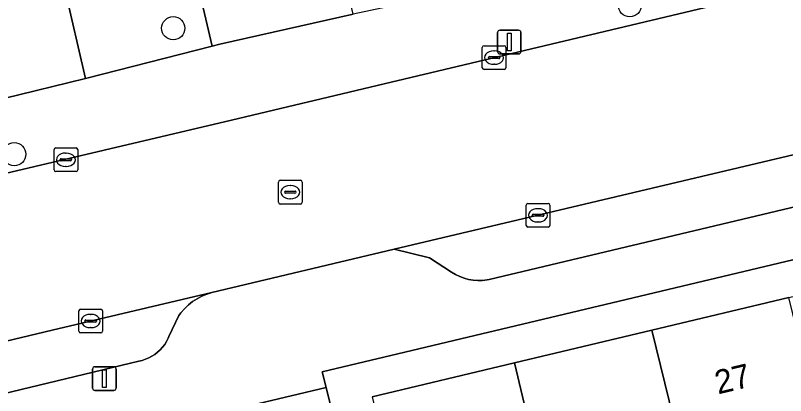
# Model space of a CAD drawing. Extents: x 158031 to 159244, y 380104 to 381214.
# Drawn here: x 158418.58 to 158451.04, y 380830.93 to 380846.95 of the extents above; entities that cross this region are included whole.
import ezdxf

# ---------------------------------------------------------------- set-up
doc = ezdxf.new("R2010")
doc.units = 0
for name, color, linetype in [('IMGEO_Boom', 7, 'Continuous'), ('IMGEO_Erf', 7, 'Continuous'), ('IMGEO_Groenvoorziening', 7, 'Continuous'), ('IMGEO_Kolk', 7, 'Continuous'), ('IMGEO_Lichtmast', 7, 'Continuous'), ('IMGEO_Pand', 7, 'Continuous'), ('IMGEO_Pand_nummerreeks', 7, 'Continuous'), ('IMGEO_Parkeervlak_open', 7, 'Continuous'), ('IMGEO_Rijbaan_lokaal_open', 7, 'Continuous'), ('IMGEO_Rioolput', 7, 'Continuous'), ('IMGEO_Voetpad_open', 7, 'Continuous')]:
    doc.layers.add(name, color=color, linetype=linetype)

msp = doc.modelspace()

# ---------------------------------------------------------------- linework, layer by layer
at = {"layer": 'IMGEO_Boom'}
for centre in [(158444.473, 380847.384), (158425.228, 380846.411), (158418.528, 380841.1)]:
    msp.add_circle(centre, 0.489, dxfattribs=at)
at = {"layer": 'IMGEO_Erf'}
for points in [[(158492.147, 380846.362), (158431.507, 380831.934), (158431.67, 380831.273), (158437.015, 380809.671), (158479.606, 380819.978)], [(158433.619, 380830.882), (158439.614, 380832.308), (158445.404, 380833.686), (158451.175, 380835.059), (158457.004, 380836.446), (158457.353, 380835.07), (158457.487, 380835.102), (158458.165, 380835.263), (158459.767, 380835.644), (158460.083, 380834.315), (158463.733, 380835.183), (158467.394, 380836.054), (158467.081, 380837.368), (158469.197, 380837.871)]]:
    msp.add_lwpolyline(points, dxfattribs=at)
at = {"layer": 'IMGEO_Groenvoorziening'}
msp.add_lwpolyline([(158426.008, 380849.326), (158421.836, 380848.384), (158420.64, 380848.128), (158421.532, 380844.298), (158426.87, 380845.655)], close=True, dxfattribs=at)
at = {"layer": 'IMGEO_Kolk'}
for p, q in [((158438.253, 380844.746), (158438.253, 380845.598)), ((158438.328, 380845.672), (158439.18, 380845.672)), ((158439.254, 380845.598), (158439.254, 380844.746)), ((158438.512, 380845.166), (158438.512, 380845.178)), ((158438.555, 380845.215), (158438.953, 380845.215)), ((158438.741, 380845.452), (158438.766, 380845.452)), ((158438.996, 380845.178), (158438.996, 380845.166)), ((158438.95, 380845.129), (158438.552, 380845.129)), ((158438.764, 380844.892), (158438.739, 380844.892)), ((158439.18, 380844.672), (158438.328, 380844.672)), ((158420.204, 380840.443), (158420.204, 380841.295)), ((158420.279, 380841.369), (158421.131, 380841.369)), ((158421.205, 380841.295), (158421.205, 380840.443)), ((158420.692, 380841.149), (158420.717, 380841.149)), ((158420.463, 380840.863), (158420.463, 380840.875)), ((158420.901, 380840.826), (158420.503, 380840.826)), ((158420.506, 380840.912), (158420.904, 380840.912)), ((158420.947, 380840.875), (158420.947, 380840.863)), ((158421.131, 380840.369), (158420.279, 380840.369)), ((158420.715, 380840.589), (158420.69, 380840.589)), ((158440.179, 380839.027), (158441.031, 380839.027)), ((158440.104, 380838.101), (158440.104, 380838.953)), ((158440.592, 380838.807), (158440.617, 380838.807)), ((158441.105, 380838.953), (158441.105, 380838.101)), ((158440.363, 380838.521), (158440.363, 380838.533)), ((158440.801, 380838.484), (158440.403, 380838.484)), ((158440.406, 380838.57), (158440.804, 380838.57)), ((158440.847, 380838.533), (158440.847, 380838.521)), ((158441.031, 380838.027), (158440.179, 380838.027)), ((158440.615, 380838.247), (158440.59, 380838.247)), ((158421.249, 380833.646), (158421.249, 380834.498)), ((158421.324, 380834.572), (158422.176, 380834.572)), ((158422.25, 380834.498), (158422.25, 380833.646)), ((158421.551, 380834.115), (158421.949, 380834.115)), ((158421.737, 380834.352), (158421.762, 380834.352)), ((158421.508, 380834.066), (158421.508, 380834.078)), ((158421.946, 380834.029), (158421.548, 380834.029)), ((158421.76, 380833.792), (158421.735, 380833.792)), ((158421.992, 380834.078), (158421.992, 380834.066)), ((158422.176, 380833.572), (158421.324, 380833.572))]:
    msp.add_line(p, q, dxfattribs=at)
for points in [[(158438.253, 380844.746), (158438.253, 380845.598)], [(158438.328, 380845.672), (158439.18, 380845.672)], [(158439.254, 380845.598), (158439.254, 380844.746)], [(158439.18, 380844.672), (158438.328, 380844.672)], [(158420.204, 380840.443), (158420.204, 380841.295)], [(158420.279, 380841.369), (158421.131, 380841.369)], [(158421.205, 380841.295), (158421.205, 380840.443)], [(158421.131, 380840.369), (158420.279, 380840.369)], [(158440.179, 380839.027), (158441.031, 380839.027)], [(158440.104, 380838.101), (158440.104, 380838.953)], [(158441.105, 380838.953), (158441.105, 380838.101)], [(158441.031, 380838.027), (158440.179, 380838.027)], [(158421.249, 380833.646), (158421.249, 380834.498)], [(158421.324, 380834.572), (158422.176, 380834.572)], [(158422.25, 380834.498), (158422.25, 380833.646)], [(158422.176, 380833.572), (158421.324, 380833.572)]]:
    msp.add_lwpolyline(points, dxfattribs=at)
for centre, radius, start, end in [((158438.33, 380845.596), 0.0765, 91.552, 178.448), ((158438.33, 380845.596), 0.0765, 91.552, 178.448), ((158439.178, 380845.596), 0.0765, 1.552, 88.448), ((158439.178, 380845.596), 0.0765, 1.552, 88.448), ((158438.552, 380845.175), 0.0403, 85.8775, 175.7526), ((158438.549, 380845.165), 0.0366, 178.938, 274.7102), ((158438.953, 380845.172), 0.043, 264.8664, 352.4533), ((158438.957, 380845.177), 0.0386, 1.7309, 96.639), ((158438.33, 380844.748), 0.0765, 181.552, 268.448), ((158438.33, 380844.748), 0.0765, 181.552, 268.448), ((158439.178, 380844.748), 0.0765, 271.552, 358.448), ((158439.178, 380844.748), 0.0765, 271.552, 358.448), ((158420.281, 380841.293), 0.0765, 91.552, 178.448), ((158420.281, 380841.293), 0.0765, 91.552, 178.448), ((158421.129, 380841.293), 0.0765, 1.552, 88.448), ((158421.129, 380841.293), 0.0765, 1.552, 88.448), ((158420.503, 380840.872), 0.0403, 85.8775, 175.7526), ((158420.5, 380840.862), 0.0366, 178.938, 274.7102), ((158420.904, 380840.869), 0.043, 264.8664, 352.4533), ((158420.908, 380840.874), 0.0386, 1.7309, 96.639), ((158420.281, 380840.445), 0.0765, 181.552, 268.448), ((158420.281, 380840.445), 0.0765, 181.552, 268.448), ((158421.129, 380840.445), 0.0765, 271.552, 358.448), ((158421.129, 380840.445), 0.0765, 271.552, 358.448), ((158440.181, 380838.951), 0.0765, 91.552, 178.448), ((158440.181, 380838.951), 0.0765, 91.552, 178.448), ((158441.029, 380838.951), 0.0765, 1.552, 88.448), ((158441.029, 380838.951), 0.0765, 1.552, 88.448), ((158440.403, 380838.53), 0.0403, 85.8775, 175.7526), ((158440.4, 380838.52), 0.0366, 178.938, 274.7102), ((158440.804, 380838.527), 0.043, 264.8664, 352.4533), ((158440.808, 380838.532), 0.0386, 1.7309, 96.639), ((158440.181, 380838.103), 0.0765, 181.552, 268.448), ((158440.181, 380838.103), 0.0765, 181.552, 268.448), ((158441.029, 380838.103), 0.0765, 271.552, 358.448), ((158441.029, 380838.103), 0.0765, 271.552, 358.448), ((158421.326, 380834.496), 0.0765, 91.552, 178.448), ((158421.326, 380834.496), 0.0765, 91.552, 178.448), ((158422.174, 380834.496), 0.0765, 1.552, 88.448), ((158422.174, 380834.496), 0.0765, 1.552, 88.448), ((158421.548, 380834.075), 0.0403, 85.8775, 175.7526), ((158421.953, 380834.077), 0.0386, 1.7309, 96.639), ((158421.545, 380834.065), 0.0366, 178.938, 274.7102), ((158421.949, 380834.072), 0.043, 264.8664, 352.4533), ((158421.326, 380833.648), 0.0765, 181.552, 268.448), ((158421.326, 380833.648), 0.0765, 181.552, 268.448), ((158422.174, 380833.648), 0.0765, 271.552, 358.448), ((158422.174, 380833.648), 0.0765, 271.552, 358.448)]:
    msp.add_arc(centre, radius, start, end, dxfattribs=at)
for centre, major_axis, ratio, start_param, end_param in [((158438.74, 380845.172), (-0.387, 0.002), 0.722429, 4.712389, 7.853982), ((158438.765, 380845.172), (-0.39, 0.002), 0.717154, 1.570796, 4.712389), ((158420.691, 380840.869), (-0.387, 0.002), 0.722429, 4.712389, 7.853982), ((158420.716, 380840.869), (-0.39, 0.002), 0.717154, 1.570796, 4.712389), ((158440.591, 380838.527), (-0.387, 0.002), 0.722429, 4.712389, 7.853982), ((158440.616, 380838.527), (-0.39, 0.002), 0.717154, 1.570796, 4.712389), ((158421.736, 380834.072), (-0.387, 0.002), 0.722429, 4.712389, 7.853982), ((158421.761, 380834.072), (-0.39, 0.002), 0.717154, 1.570796, 4.712389)]:
    msp.add_ellipse(centre, major_axis=major_axis, ratio=ratio, start_param=start_param, end_param=end_param, dxfattribs=at)
at = {"layer": 'IMGEO_Lichtmast'}
for p, q in [((158438.896, 380845.429), (158438.896, 380846.229)), ((158438.896, 380846.229), (158438.896, 380845.429)), ((158438.996, 380846.329), (158439.786, 380846.329)), ((158439.786, 380846.329), (158438.996, 380846.329)), ((158439.886, 380846.229), (158439.886, 380845.429)), ((158439.886, 380845.429), (158439.886, 380846.229)), ((158439.786, 380845.329), (158438.996, 380845.329)), ((158438.996, 380845.329), (158439.786, 380845.329)), ((158421.829, 380831.247), (158421.829, 380832.047)), ((158421.829, 380832.047), (158421.829, 380831.247)), ((158421.929, 380832.147), (158422.719, 380832.147)), ((158422.719, 380832.147), (158421.929, 380832.147)), ((158422.819, 380832.047), (158422.819, 380831.247)), ((158422.819, 380831.247), (158422.819, 380832.047)), ((158422.719, 380831.147), (158421.929, 380831.147)), ((158421.929, 380831.147), (158422.719, 380831.147))]:
    msp.add_line(p, q, dxfattribs=at)
for points in [[(158439.316, 380846.204), (158439.466, 380846.204), (158439.466, 380845.454), (158439.316, 380845.454), (158439.316, 380846.204)], [(158422.249, 380832.022), (158422.399, 380832.022), (158422.399, 380831.272), (158422.249, 380831.272), (158422.249, 380832.022)]]:
    msp.add_lwpolyline(points, dxfattribs=at)
for centre, start, end in [((158438.996, 380846.229), 90, 180), ((158438.996, 380846.229), 90, 180), ((158439.786, 380846.229), 0, 90), ((158439.786, 380846.229), 360, 90), ((158438.996, 380845.429), 180, 270), ((158438.996, 380845.429), 180, 270), ((158439.786, 380845.429), 270, 0), ((158439.786, 380845.429), 270, 0), ((158421.929, 380832.047), 90, 180), ((158421.929, 380832.047), 90, 180), ((158422.719, 380832.047), 0, 90), ((158422.719, 380832.047), 360, 90), ((158421.929, 380831.247), 180, 270), ((158421.929, 380831.247), 180, 270), ((158422.719, 380831.247), 270, 0), ((158422.719, 380831.247), 270, 0)]:
    msp.add_arc(centre, 0.1, start, end, dxfattribs=at)
at = {"layer": 'IMGEO_Pand'}
for points in [[(158451.175, 380835.059), (158445.404, 380833.686), (158447.591, 380824.752), (158451.78, 380825.749), (158453.052, 380820.399), (158454.671, 380820.784)], [(158442.999, 380818.07), (158444.915, 380818.526), (158443.656, 380823.816), (158447.591, 380824.752), (158445.404, 380833.686), (158439.614, 380832.308)], [(158442.999, 380818.07), (158439.614, 380832.308), (158433.619, 380830.882), (158434.776, 380826.018), (158435.727, 380822.023), (158440.038, 380823.049), (158441.318, 380817.67)]]:
    msp.add_lwpolyline(points, close=True, dxfattribs=at)
at = {"layer": 'IMGEO_Parkeervlak_open'}
msp.add_lwpolyline([(158470.273, 380843.365), (158469.788, 380845.423), (158465.626, 380844.441), (158434.542, 380837.096), (158436.031, 380836.73), (158436.953, 380836.125), (158437.123, 380836.027), (158437.302, 380835.944), (158437.487, 380835.878), (158437.678, 380835.828), (158437.872, 380835.796), (158438.068, 380835.781), (158438.265, 380835.783), (158438.46, 380835.804), (158438.55, 380835.819)], close=True, dxfattribs=at)
msp.add_lwpolyline([(158403.115, 380827.409), (158423.774, 380832.383), (158423.919, 380832.415), (158424.061, 380832.459), (158424.199, 380832.516), (158424.33, 380832.585), (158424.455, 380832.666), (158424.572, 380832.757), (158424.681, 380832.859), (158424.78, 380832.97), (158424.869, 380833.089), (158424.947, 380833.216), (158425.013, 380833.349), (158425.04, 380833.413), (158425.467, 380834.31), (158425.552, 380834.422), (158425.702, 380834.592), (158425.866, 380834.748), (158426.044, 380834.89), (158426.234, 380835.014), (158426.434, 380835.121), (158426.643, 380835.21), (158426.859, 380835.28), (158420.125, 380833.689), (158384.586, 380825.186)], dxfattribs=at)
at = {"layer": 'IMGEO_Rijbaan_lokaal_open'}
for points in [[(158422.216, 380891.65), (158450.904, 380898.43), (158446.846, 380916.284), (158412.391, 380908.116), (158412.316, 380908.434), (158411.93, 380908.345), (158412.805, 380904.563), (158413.211, 380904.66), (158421.49, 380869.778), (158423.115, 380862.932), (158426.327, 380849.398), (158426.008, 380849.326), (158426.87, 380845.655), (158427.196, 380845.738), (158432.809, 380847.002)], [(158382.955, 380824.821), (158384.586, 380825.186), (158420.125, 380833.689), (158426.859, 380835.28), (158434.542, 380837.096), (158465.626, 380844.441), (158469.788, 380845.423), (158468.191, 380852.193), (158458.51, 380849.883), (158455.24, 380849.102), (158434.124, 380844.068), (158427.688, 380842.533), (158381.334, 380831.623)]]:
    msp.add_lwpolyline(points, close=True, dxfattribs=at)
at = {"layer": 'IMGEO_Rioolput'}
for p, q in [((158429.739, 380840.003), (158430.591, 380840.003)), ((158429.664, 380839.077), (158429.664, 380839.929)), ((158430.152, 380839.783), (158430.177, 380839.783)), ((158430.665, 380839.929), (158430.665, 380839.077)), ((158429.923, 380839.497), (158429.923, 380839.509)), ((158430.361, 380839.46), (158429.963, 380839.46)), ((158429.966, 380839.546), (158430.364, 380839.546)), ((158430.407, 380839.509), (158430.407, 380839.497)), ((158430.591, 380839.003), (158429.739, 380839.003)), ((158430.175, 380839.223), (158430.15, 380839.223))]:
    msp.add_line(p, q, dxfattribs=at)
for points in [[(158429.739, 380840.003), (158430.591, 380840.003)], [(158429.664, 380839.077), (158429.664, 380839.929)], [(158430.665, 380839.929), (158430.665, 380839.077)], [(158430.591, 380839.003), (158429.739, 380839.003)]]:
    msp.add_lwpolyline(points, dxfattribs=at)
for centre, radius, start, end in [((158429.741, 380839.927), 0.0765, 91.552, 178.448), ((158429.741, 380839.927), 0.0765, 91.552, 178.448), ((158430.589, 380839.927), 0.0765, 1.552, 88.448), ((158430.589, 380839.927), 0.0765, 1.552, 88.448), ((158429.963, 380839.506), 0.0403, 85.8775, 175.7526), ((158429.96, 380839.496), 0.0366, 178.938, 274.7102), ((158430.364, 380839.503), 0.043, 264.8664, 352.4533), ((158430.368, 380839.508), 0.0386, 1.7309, 96.639), ((158429.741, 380839.079), 0.0765, 181.552, 268.448), ((158429.741, 380839.079), 0.0765, 181.552, 268.448), ((158430.589, 380839.079), 0.0765, 271.552, 358.448), ((158430.589, 380839.079), 0.0765, 271.552, 358.448)]:
    msp.add_arc(centre, radius, start, end, dxfattribs=at)
for centre, major_axis, ratio, start_param, end_param in [((158430.151, 380839.503), (-0.387, 0.002), 0.722429, 4.712389, 7.853982), ((158430.176, 380839.503), (-0.39, 0.002), 0.717154, 1.570796, 4.712389)]:
    msp.add_ellipse(centre, major_axis=major_axis, ratio=ratio, start_param=start_param, end_param=end_param, dxfattribs=at)
at = {"layer": 'IMGEO_Voetpad_open'}
for points in [[(158417.391, 380843.287), (158421.532, 380844.298), (158420.64, 380848.128), (158421.836, 380848.384), (158418.721, 380861.995), (158423.115, 380862.932), (158421.49, 380869.778), (158417.003, 380868.676)], [(158380.219, 380831.378), (158381.334, 380831.623), (158427.688, 380842.533), (158434.124, 380844.068), (158455.24, 380849.102), (158458.51, 380849.883), (158468.191, 380852.193), (158470.875, 380852.834), (158500, 380859.786), (158501.877, 380860.234), (158519.469, 380864.387)], [(158500, 380862.796), (158459.414, 380853.223), (158457.923, 380852.871), (158455.017, 380852.184), (158447.832, 380850.462), (158439.088, 380848.395), (158436.196, 380847.728), (158432.809, 380847.002), (158427.196, 380845.738), (158426.87, 380845.655), (158421.532, 380844.298), (158417.391, 380843.287), (158378.748, 380834.154)], [(158382.15, 380819.43), (158403.689, 380824.581), (158405.227, 380824.949), (158428.782, 380830.582), (158431.67, 380831.273), (158431.507, 380831.934), (158492.147, 380846.362), (158492.306, 380845.603), (158500, 380847.433), (158527.386, 380853.947), (158531.949, 380855.031), (158535.255, 380855.756), (158554.603, 380860.32)], [(158470.273, 380843.365), (158438.55, 380835.819), (158438.46, 380835.804), (158438.265, 380835.783), (158438.068, 380835.781), (158437.872, 380835.796), (158437.678, 380835.828), (158437.487, 380835.878), (158437.302, 380835.944), (158437.123, 380836.027), (158436.953, 380836.125), (158436.031, 380836.73), (158434.542, 380837.096), (158426.859, 380835.28), (158426.643, 380835.21), (158426.434, 380835.121), (158426.234, 380835.014), (158426.044, 380834.89), (158425.866, 380834.748), (158425.702, 380834.592), (158425.552, 380834.422), (158425.467, 380834.31), (158425.04, 380833.413), (158425.013, 380833.349), (158424.947, 380833.216), (158424.869, 380833.089), (158424.78, 380832.97), (158424.681, 380832.859), (158424.572, 380832.757), (158424.455, 380832.666), (158424.33, 380832.585), (158424.199, 380832.516), (158424.061, 380832.459), (158423.919, 380832.415), (158423.774, 380832.383), (158403.115, 380827.409)]]:
    msp.add_lwpolyline(points, dxfattribs=at)
msp.add_lwpolyline([(158431.67, 380831.273), (158428.782, 380830.582), (158429.711, 380827.189), (158430.868, 380822.325), (158431.806, 380818.384), (158434.234, 380808.176), (158434.604, 380806.62), (158433.455, 380806.347), (158433.684, 380805.383), (158434.842, 380800.518), (158435.99, 380800.791), (158439.034, 380801.514), (158437.377, 380808.21), (158437.015, 380809.671)], close=True, dxfattribs=at)

# ---------------------------------------------------------------- texts
at = {"layer": 'IMGEO_Pand_nummerreeks'}
msp.add_text('27', height=1, rotation=13.3836, dxfattribs=at).set_placement((158448.191, 380830.977))

doc.saveas('drawing.dxf')
